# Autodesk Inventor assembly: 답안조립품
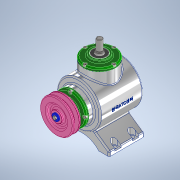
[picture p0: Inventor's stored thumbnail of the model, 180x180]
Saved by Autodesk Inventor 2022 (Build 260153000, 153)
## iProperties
Created: 2023-04
Part Number: 답안조립품
Document SubType Name: Assembly
Designer: Admin
Author: Admin
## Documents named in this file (17)
- C:\Users\Admin\Desktop\730411V1017\답안조립품.iam
- C:\Users\Admin\Desktop\730411V1017\본체.ipt
- C:\Users\Admin\Desktop\730411V1017\커버.ipt
- C:\Users\Admin\Desktop\730411V1017\베어링 6203.ipt
- C:\Users\Admin\Desktop\730411V1017\오일실 17 x 32 x 8.ipt
- C:\Users\Admin\Desktop\730411V1017\메인 축.ipt
- 메인 축.ipt
- C:\Users\Admin\Desktop\730411V1017\Ű 5 x 5 x 14.ipt
- C:\Users\Admin\Desktop\730411V1017\메인 베벨기어.ipt
- C:\Users\Admin\Desktop\730411V1017\서브 축.ipt
- 서브 축.ipt
- C:\Users\Admin\Desktop\730411V1017\Ű 4 x 4 x 14.ipt
- C:\Users\Admin\Desktop\730411V1017\서브 베벨기어.ipt
- C:\Users\Admin\Desktop\730411V1017\V-벨트풀리.ipt
- C:\Users\Admin\Desktop\730411V1017\볼트 M4 x 10.ipt
- C:\Users\Admin\Desktop\730411V1017\와셔 4 x 16.ipt
- C:\Users\Admin\Desktop\730411V1017\육각볼트 M4 x 8.ipt
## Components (4 placed, 3 different names)
1. Ű 5 x 5 x 14:1
2. Ű 4 x 4 x 14:1
3. Ű 4 x 4 x 14:2
4. V-벨트풀리:1
